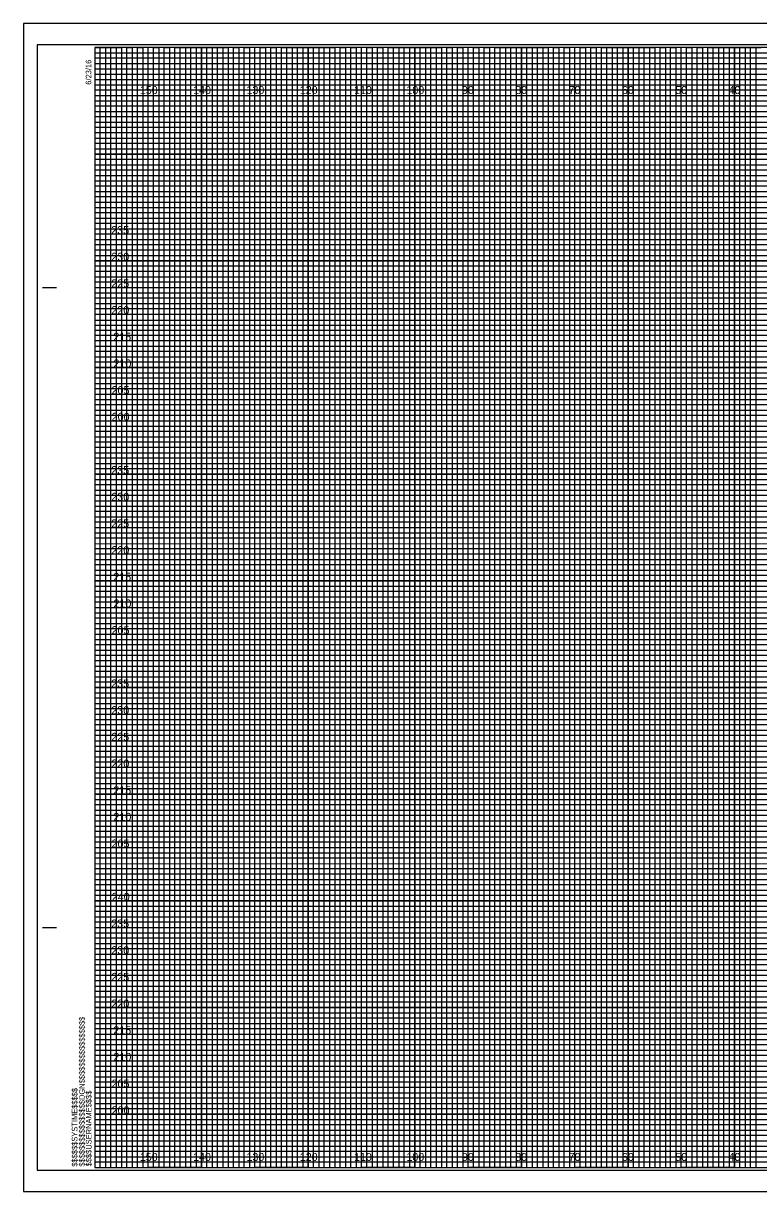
# Model space of a CAD drawing. Extents: x -13 to 323, y -5 to 654.
# Drawn here: x -13.4 to 124.5, y -4.5 to 214.5 of the extents above; entities that cross this region are included whole.
import ezdxf

# ---------------------------------------------------------------- set-up
doc = ezdxf.new("R2010")
doc.units = 0
for name, color, linetype in [('Prop XS Elevation Labels', 7, 'Continuous'), ('Prop XS Offset Labels', 7, 'Continuous'), ('Sheet Cross Section CELL', 7, 'Continuous'), ('Sheet Cross Section Grid Major CELL', 7, 'Continuous'), ('Sheet Cross Section Grid Middle CELL', 7, 'Continuous'), ('Sheet Cross Section Grid Minor 1 CELL', 7, 'Continuous'), ('Sheet Cross Section Grid Minor 2 CELL', 7, 'Continuous'), ('Sheet Cutting Line CELL', 7, 'Continuous'), ('Sheet DOT Grid CELL', 7, 'Continuous'), ('Sheet Plot Border Inside CELL', 7, 'Continuous'), ('Sheet Plot Border Outside CELL', 7, 'Continuous')]:
    doc.layers.add(name, color=color, linetype=linetype)

msp = doc.modelspace()

# ---------------------------------------------------------------- linework, layer by layer
at = {"layer": 'Sheet Cross Section CELL'}
for p, q in [((-9.8, 165), (-7.3, 165)), ((-9.7, 165), (-7.2, 165)), ((-9.8, 45), (-7.3, 45)), ((-9.7, 45), (-7.2, 45)), ((0, 0), (0, 0)), ((0, 0), (0, 0)), ((0, 0), (0, 0)), ((0, 0), (0, 0)), ((0, 0), (0, 0)), ((0, 0), (0, 0)), ((0, 0), (0, 0))]:
    msp.add_line(p, q, dxfattribs=at)
msp.add_lwpolyline([(320, 210), (0, 210), (0, 0), (320, 0)], close=True, dxfattribs=at)
at = {"layer": 'Sheet Cross Section Grid Major CELL'}
for p, q in [((10, 210), (0, 210)), ((10, 0), (10, 210)), ((30, 210), (20, 210)), ((20, 210), (20, 0)), ((30, 0), (30, 210)), ((50, 210), (40, 210)), ((40, 210), (40, 0)), ((50, 0), (50, 210)), ((70, 210), (60, 210)), ((60, 210), (60, 0)), ((70, 0), (70, 210)), ((90, 210), (80, 210)), ((80, 210), (80, 0)), ((90, 0), (90, 210)), ((110, 210), (100, 210)), ((100, 210), (100, 0)), ((110, 0), (110, 210)), ((130, 210), (120, 210)), ((120, 210), (120, 0)), ((20, 0), (10, 0)), ((40, 0), (30, 0)), ((60, 0), (50, 0)), ((80, 0), (70, 0)), ((100, 0), (90, 0)), ((120, 0), (110, 0))]:
    msp.add_line(p, q, dxfattribs=at)
for points in [[(0, 200), (320, 200), (320, 190), (0, 190)], [(0, 180), (320, 180), (320, 170), (0, 170)], [(0, 160), (320, 160), (320, 150), (0, 150)], [(0, 140), (320, 140), (320, 130), (0, 130)], [(0, 120), (320, 120), (320, 110), (0, 110)], [(0, 100), (320, 100), (320, 90), (0, 90)], [(0, 80), (320, 80), (320, 70), (0, 70)], [(0, 60), (320, 60), (320, 50), (0, 50)], [(0, 40), (320, 40), (320, 30), (0, 30)], [(0, 20), (320, 20), (320, 10), (0, 10)]]:
    msp.add_lwpolyline(points, dxfattribs=at)
at = {"layer": 'Sheet Cross Section Grid Middle CELL'}
for points in [[(0, 210), (5, 210), (5, 0), (15, 0), (15, 210), (25, 210), (25, 0), (35, 0), (35, 210), (45, 210), (45, 0), (55, 0), (55, 210), (65, 210), (65, 0), (75, 0), (75, 210), (85, 210), (85, 0), (95, 0), (95, 210), (105, 210), (105, 0), (115, 0), (115, 210), (125, 210)], [(0, 205), (275, 205)], [(0, 185), (320, 185), (320, 195), (0, 195)], [(0, 165), (320, 165), (320, 175), (0, 175)], [(0, 145), (320, 145), (320, 155), (0, 155)], [(0, 125), (320, 125), (320, 135), (0, 135)], [(0, 105), (320, 105), (320, 115), (0, 115)], [(0, 85), (320, 85), (320, 95), (0, 95)], [(0, 65), (320, 65), (320, 75), (0, 75)], [(0, 45), (320, 45), (320, 55), (0, 55)], [(0, 25), (320, 25), (320, 35), (0, 35)], [(0, 5), (320, 5), (320, 15), (0, 15)]]:
    msp.add_lwpolyline(points, dxfattribs=at)
at = {"layer": 'Sheet Cross Section Grid Minor 1 CELL'}
for p, q in [((0, 209), (260, 209)), ((260, 207.98), (0, 207.98)), ((0, 207.98), (0, 207)), ((0, 207), (260, 207)), ((260, 205.89), (0, 205.89)), ((0, 205.89), (0, 204)), ((0, 204), (320, 204))]:
    msp.add_line(p, q, dxfattribs=at)
for points in [[(0, 203), (270, 203), (320, 203), (320, 202), (0, 202)], [(0, 201), (320, 201), (320, 199), (0, 199)], [(0, 198), (320, 198), (320, 197), (0, 196.98)], [(0, 196), (320, 196), (320, 194), (0, 194)], [(0, 193), (320, 193), (320, 192), (0, 192)], [(0, 191), (320, 191), (320, 189), (0, 189)], [(0, 188), (320, 188), (320, 187), (0, 187)], [(0, 186), (320, 186), (320, 184), (0, 184)], [(0, 183), (320, 183), (320, 182), (0, 182)], [(0, 181), (320, 181), (320, 179), (0, 179)], [(0, 178), (320, 178), (320, 177), (0, 177)], [(0, 176), (320, 176), (320, 173.95), (320, 173), (320, 172), (0, 172)], [(0, 174), (320, 174), (320, 173), (0, 173)], [(0, 171), (320, 171), (320, 169), (0, 169.03)], [(0, 169.03), (320, 169), (320, 168), (0, 168)], [(0, 167), (320, 167), (320, 166), (0, 166)], [(0, 164), (320, 164), (320, 163), (0, 163)], [(0, 162), (320, 162), (320, 161), (0, 161)], [(-0.07, 158.89), (320, 158.89), (320, 157.88), (-0.07, 157.88)], [(0, 157), (320, 157), (320, 156), (0, 156)], [(0, 154), (320, 154), (320, 153), (0, 153)], [(0, 152), (320, 152), (320, 151), (0, 151)], [(0, 149), (320, 149), (320, 148), (0, 148)], [(0, 147), (320, 147), (320, 146), (0, 146)], [(0, 144), (320, 144), (320, 143), (0, 143)], [(0, 142), (320, 142), (320, 141), (0, 141)], [(0, 139), (320, 139), (319.99, 137.98), (0, 138)], [(0, 137), (320, 137), (320, 136), (0, 136)], [(0, 134), (320, 134), (320, 133), (0, 133)], [(0, 132), (320, 132), (320, 131), (0, 131)], [(0, 129), (320, 129), (320, 128), (0, 128)], [(0, 127), (320, 127), (320, 126), (0, 126)], [(0, 124), (320, 124), (320, 123), (0, 123)], [(0, 122), (320, 122), (320, 121), (0, 121)], [(0, 119), (320, 119), (320, 118), (0, 118)], [(0, 116.99), (320.07, 116.91), (320, 116), (0, 116)], [(0, 114), (320, 114), (320, 113), (0, 113)], [(0, 112), (320, 112), (320, 111), (0, 111)], [(0, 109), (320, 109), (320, 108), (0, 108)], [(0, 107), (320, 107), (320, 106), (0, 106)], [(0, 104), (320, 104), (320, 103), (0, 103)], [(0, 102), (320, 102), (320, 101), (0, 101)], [(0, 99), (320, 99), (320, 98), (0, 98)], [(0, 97), (320, 97), (320, 96), (0, 96)], [(0, 94), (320, 94), (320, 93), (0, 93)], [(0, 92), (320, 92), (320, 91), (0, 91)], [(0, 89), (320, 89), (320, 88), (0, 88)], [(0, 87), (320, 87), (320, 86), (0, 86)], [(0, 84), (320, 84), (320, 83), (0, 83)], [(0, 82), (320, 82), (320, 81), (0, 81)], [(0, 79), (320, 79), (319.99, 77.98), (0, 78)], [(0, 77), (320, 77), (320, 76), (0, 76)], [(0, 74), (320, 74), (320, 73), (0, 73)], [(0, 72), (320, 72), (320, 71), (0, 71)], [(0, 69), (320, 69), (320, 68), (0, 68)], [(0, 67), (320, 67), (320, 66), (0, 66)], [(0, 64), (320, 64), (320, 63), (0, 63)], [(0, 62), (320, 62), (320, 61), (0, 61)], [(0, 59), (320, 59), (320, 58), (0, 58)], [(0, 56.99), (320.07, 56.91), (320, 56), (0, 56)], [(0, 54), (320, 54), (320, 53), (0, 53)], [(0, 52), (320, 52), (320, 51), (0, 51)], [(0, 49), (320, 49), (320, 48), (0, 48)], [(0, 47), (320, 47), (320, 46), (0, 46)], [(0, 44), (320, 44), (320, 43), (0, 43)], [(0, 42), (320, 42), (320, 41), (0, 41)], [(0, 39), (320, 39), (320, 38), (0, 38)], [(0, 37), (320, 37), (320, 36), (0, 36)], [(0, 34), (320, 34), (320, 33), (0, 33)], [(0, 32), (320, 32), (320, 31), (0, 31)], [(0, 29), (320, 29), (320, 28), (0, 28)], [(0, 27), (320, 27), (320, 26), (0, 26)], [(0, 24), (320, 24), (320, 23), (0, 23)], [(0, 22), (320, 22), (320, 21), (0, 21)], [(0, 19), (320, 19), (320, 18), (0, 18)], [(0, 17), (320, 17), (320, 16), (0, 16)], [(0, 14), (320, 14), (320, 13), (0, 13)], [(0, 12), (320, 12), (320, 11), (0, 11)], [(0, 9), (320, 9), (320, 8), (0, 8)], [(0, 7), (320, 7), (320, 6), (0, 6)], [(0, 4), (320, 4), (320, 3), (0, 3)], [(0, 2), (320, 2), (320, 1), (0, 1)]]:
    msp.add_lwpolyline(points, dxfattribs=at)
at = {"layer": 'Sheet Cross Section Grid Minor 2 CELL'}
for points in [[(0, 0), (1, 0), (1, 210), (2, 210), (2, 0)], [(2, 0), (3, 0), (3, 210), (4, 210), (4, 0)], [(5, 0), (6, 0), (6, 210), (7, 210), (7, 0)], [(7, 0), (8, 0), (8, 210), (9, 210), (9, 0)], [(10, 0), (11, 0), (11, 210), (12, 210), (12, 0)], [(12, 0), (13, 0), (13, 210), (14, 210), (14, 0)], [(15, 0), (16, 0), (16, 210), (17, 210), (17, 0)], [(17, 0), (18, 0), (18, 210), (19, 210), (19, 0)], [(20, 0), (21, 0), (21, 210), (22, 210), (22, 0)], [(22, 0), (23, 0), (23, 210), (24, 210), (24, 0)], [(25, 0), (26, 0), (26, 210), (27, 210), (27, 0)], [(27, 0), (28, 0), (28, 210), (29, 210), (29, 0)], [(30, 0), (31, 0), (31, 210), (32, 210), (32, 0)], [(32, 0), (33, 0), (33, 210), (34, 210), (34, 0)], [(35, 0), (36, 0), (36, 210), (37, 210), (37, 0)], [(37, 0), (38, 0), (38, 210), (39, 210), (39, 0)], [(40, 0), (41, 0), (41, 210), (42, 210), (42, 0)], [(42, 0), (43, 0), (43, 210), (44, 210), (44, 0)], [(45, 0), (46, 0), (46, 210), (47, 210), (47, 0)], [(47, 0), (48, 0), (48, 210), (49, 210), (49, 0)], [(50, 0), (51, 0), (51, 210), (52, 210), (52, 0)], [(52, 0), (53, 0), (53, 210), (54, 210), (54, 0)], [(55, 0), (56, 0), (56, 210), (57, 210), (57, 0)], [(57, 0), (58, 0), (58, 210), (59, 210), (59, 0)], [(60, 0), (61, 0), (61, 210), (62, 210), (62, 0)], [(62, 0), (63, 0), (63, 210), (64, 210), (64, 0)], [(65, 0), (66, 0), (66, 210), (67, 210), (67, 0)], [(67, 0), (68, 0), (68, 210), (69, 210), (69, 0)], [(70, 0), (71, 0), (71, 210), (72, 210), (72, 0)], [(72, 0), (73, 0), (73, 210), (74, 210), (74, 0)], [(75, 0), (76, 0), (76, 210), (77, 210), (77, 0)], [(77, 0), (78, 0), (78, 210), (79, 210), (79, 0)], [(80, 0), (81, 0), (81, 210), (82, 210), (82, 0)], [(82, 0), (83, 0), (83, 210), (84, 210), (84, 0)], [(85, 0), (86, 0), (86, 210), (87, 210), (87, 0)], [(87, 0), (88, 0), (88, 210), (89, 210), (89, 0)], [(90, 0), (91, 0), (91, 210), (92, 210), (92, 0)], [(92, 0), (93, 0), (93, 210), (94, 210), (94, 0)], [(95, 0), (96, 0), (96, 210), (97, 210), (97, 0)], [(97, 0), (98, 0), (98, 210), (99, 210), (99, 0)], [(100, 0), (101, 0), (101, 210), (102, 210), (102, 0)], [(102, 0), (103, 0), (103, 210), (104, 210), (104, 0)], [(105, 0), (106, 0), (106, 210), (107, 210), (107, 0)], [(107, 0), (108, 0), (108, 210), (109, 210), (109, 0)], [(110, 0), (111, 0), (111, 210), (112, 210), (112, 0)], [(112, 0), (113, 0), (113, 210), (114, 210), (114, 0)], [(115, 0), (116, 0), (116, 210), (117, 210), (117, 0)], [(117, 0), (118, 0), (118, 210), (119, 210), (119, 0)], [(120, 0), (121, 0), (121, 210), (122, 210), (122, 0)], [(122, 0), (123, 0), (123, 210), (124, 210), (124, 0)]]:
    msp.add_lwpolyline(points, dxfattribs=at)
at = {"layer": 'Sheet Cutting Line CELL'}
for p, q in [((323.3, 214.5), (-13.4, 214.5)), ((-13.4, 214.5), (-13.4, -4.5)), ((-13.4, -4.5), (323.3, -4.5))]:
    msp.add_line(p, q, dxfattribs=at)
at = {"layer": 'Sheet DOT Grid CELL'}
for p, q in [((10, 0), (10, 210)), ((20, 0), (20, 210)), ((30, 0), (30, 210)), ((40, 0), (40, 210)), ((50, 0), (50, 210)), ((60, 0), (60, 210)), ((70, 0), (70, 210)), ((80, 0), (80, 210)), ((90, 0), (90, 210)), ((100, 0), (100, 210)), ((110, 0), (110, 210)), ((120, 0), (120, 210)), ((0, 200), (320, 200)), ((0, 190), (320, 190)), ((0, 180), (320, 180)), ((0, 170), (320, 170)), ((0, 160), (320, 160)), ((0, 150), (320, 150)), ((0, 140), (320, 140)), ((0, 130), (320, 130)), ((0, 120), (320, 120)), ((0, 110), (320, 110)), ((0, 100), (320, 100)), ((0, 90), (320, 90)), ((0, 80), (320, 80)), ((0, 70), (320, 70)), ((0, 60), (320, 60)), ((0, 50), (320, 50)), ((0, 40), (320, 40)), ((0, 30), (320, 30)), ((0, 20), (320, 20)), ((0, 10), (320, 10))]:
    msp.add_line(p, q, dxfattribs=at)
at = {"layer": 'Sheet Plot Border Inside CELL'}
msp.add_lwpolyline([(-10.8, -0.5), (322.4, -0.5), (322.4, 210.5), (-10.8, 210.5)], close=True, dxfattribs=at)
at = {"layer": 'Sheet Plot Border Outside CELL'}
msp.add_lwpolyline([(-13.4, -4.5), (323.3, -4.5), (323.3, 214.5), (-13.4, 214.5)], close=True, dxfattribs=at)

# ---------------------------------------------------------------- texts
at = {"layer": 'Prop XS Elevation Labels'}
for s, p in [('235', (3.09, 175)), ('230', (3.11, 170)), ('225', (3.1, 165)), ('220', (3.12, 160)), ('215', (3.48, 155)), ('210', (3.5, 150)), ('205', (3.15, 145)), ('200', (3.17, 140)), ('235', (3.09, 130)), ('230', (3.11, 125)), ('225', (3.1, 120)), ('220', (3.12, 115)), ('215', (3.48, 110)), ('210', (3.5, 105)), ('205', (3.15, 100)), ('235', (3.09, 90)), ('230', (3.11, 85)), ('225', (3.1, 80)), ('220', (3.12, 75)), ('215', (3.48, 70)), ('210', (3.5, 65)), ('205', (3.15, 60)), ('240', (3.19, 50)), ('235', (3.09, 45)), ('230', (3.11, 40)), ('225', (3.1, 35)), ('220', (3.12, 30)), ('215', (3.48, 25)), ('210', (3.5, 20)), ('205', (3.15, 15)), ('200', (3.17, 10))]:
    msp.add_text(s, height=1.5, dxfattribs=at).set_placement(p)
at = {"layer": 'Prop XS Offset Labels'}
for s, p in [('150', (8.44, 201.25)), ('140', (18.44, 201.25)), ('130', (28.44, 201.25)), ('120', (38.44, 201.25)), ('110', (48.62, 201.25)), ('100', (58.44, 201.25)), ('90', (68.86, 201.25)), ('80', (78.86, 201.25)), ('70', (88.86, 201.25)), ('60', (98.86, 201.25)), ('50', (108.86, 201.25)), ('40', (118.86, 201.25)), ('150', (8.44, 1.25)), ('140', (18.44, 1.25)), ('130', (28.44, 1.25)), ('120', (38.44, 1.25)), ('110', (48.62, 1.25)), ('100', (58.44, 1.25)), ('90', (68.86, 1.25)), ('80', (78.86, 1.25)), ('70', (88.86, 1.25)), ('60', (98.86, 1.25)), ('50', (108.86, 1.25)), ('40', (118.86, 1.25))]:
    msp.add_text(s, height=1.5, dxfattribs=at).set_placement(p)
at = {"layer": 'Sheet Cross Section CELL'}
for s, p in [('6/23/16', (-0.65, 203)), ('$$$$$$$$$$$$$$$$DGN$$$$$$$$$$$$$$$$', (-1.88, 0.18)), ('$$$$$$SYSTIME$$$$$', (-3.26, 0.18)), ('$$$$USERNAME$$$$', (-0.62, 0.23))]:
    msp.add_text(s, height=1.05, rotation=90, dxfattribs=at).set_placement(p)

doc.saveas('drawing.dxf')
